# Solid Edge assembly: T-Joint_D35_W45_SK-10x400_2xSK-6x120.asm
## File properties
Author: fknapp
Template: iso metric assembly.asm
Last saved by: fknapp
Revision: 16
Application: Solid Edge
Username: fknapp
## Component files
T-Joint_D35_W45.par
SK Schraube 6x120_ohne_Gewinde.par
SK Schraube 10x400_ohne_Gewinde_22042020.par
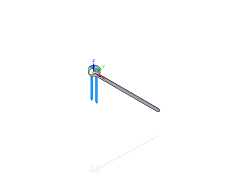
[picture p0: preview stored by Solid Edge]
